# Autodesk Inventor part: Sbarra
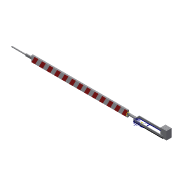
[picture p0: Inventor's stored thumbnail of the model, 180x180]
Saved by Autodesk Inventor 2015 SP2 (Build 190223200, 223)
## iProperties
Created: 2017-10
Part Number: Sbarra
Material: Generico
Document SubType Name: Modeling
Designer: Massimo Pizzirani
Density: 1 g/cm^3
Appearance: Default
Author: Massimo Pizzirani
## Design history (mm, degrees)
sketch "Schizzo1"
  geometry: L1 (250, -125)-(-250, -125); L2 (-250, -125)-(-250, 125); L3 (-250, 125)-(250, 125); L4 (250, 125)-(250, -125); L5 (250, -125)-(-250, 125); L6 (-250, -125)-(250, 125); L7 (1156.676, -150)-(-275, -150); L8 (-275, -150)-(-275, 150); L9 (-275, 150)-(1156.676, 150); L10 (-250, 125)-(1156.676, 125); L11 (-250, -125)-(1156.676, -125); L12 (1156.676, 150)-(1156.676, 125); L13 (1156.676, -125)-(1156.676, -150); 1 further point
  constraints: 26 end point, 3 parallel, 2 midpoint, 2 perpendicular, 2 point on line, 2 vertical, 1 collinear, 1 horizontal
  dimensions: "d0" = 250 distance of L1.end L2.end; "d1" = 500 distance of L1.start L1.end
extrude "Estrusione1" new body sketch "Schizzo1" distance "d3" = 100; taper "d4" = 0 deg
sketch "Schizzo2"
  geometry: L1 (0, 0)-(0, 100) reference; L2 (0, 50)-(1431.676, 50); L3 (1431.676, 0)-(1431.676, 100) reference; C1 r 25 at (500, 50); 1 further point
  constraints: 2 end point, 2 midpoint, 1 centre point, 1 point on line
  dimensions: "d5" = 50 diameter of C1; "d8" = 500 distance from line of L1 C1.centre
extrude "Estrusione2" cut sketch "Schizzo2" stored distance "d6" = 0; taper "d7" = 0 deg
sketch "Schizzo3"
  geometry: L1 (0, 300)-(0, 0) reference; L2 (0, 0)-(100, 0) reference; L3 (100, 300)-(100, 0) reference; L4 (0, 300)-(100, 300) reference; C1 r 50 at (50, 150); 1 further point
  constraints: 1 centre point
extrude "Estrusione3" join sketch "Schizzo3" distance "d9" = 200; taper "d10" = 0 deg
node "Piano di lavoro1"
sketch "Schizzo4"
  geometry: L1 (50, -25)-(-50, -25); L2 (-50, -25)-(-50, 25); L3 (-50, 25)-(50, 25); L4 (50, 25)-(50, -25); L5 (50, -25)-(-50, 25); L6 (-50, -25)-(50, 25); 2 further points
  constraints: 12 end point, 2 midpoint, 2 parallel, 1 horizontal, 1 perpendicular
  dimensions: "d12" = 100 distance of L2.end L3.end; "d13" = 50 distance of L1.end L2.end
loft "Loft1" sketch "Schizzo4" dims "d14" = 0, "d15" = 90 deg, "d16" = 0, "d17" = 90 deg
  node "Spigoli1"
sketch "Schizzo5"
  geometry: L1 (0, 0)-(0, 50) reference; L2 (0, 50)-(-100, 50) reference; L3 (-100, 50)-(-100, 0) reference; L4 (-100, 0)-(0, 0) reference; L5 (0, 50)-(-100, 0); L6 (-200, -10)-(100, -10); L7 (100, -10)-(100, 60); L8 (100, 60)-(-200, 60); L9 (-200, 60)-(-200, -10); L10 (-200, -10)-(100, 60); L11 (100, -10)-(-200, 60); 2 further points
  constraints: 14 end point, 3 midpoint, 2 parallel, 1 horizontal, 1 perpendicular
  dimensions: "d18" = 300 distance of L8.end L7.end; "d19" = 70 distance of L7.end L6.end
extrude "Estrusione4" join sketch "Schizzo5" distance "d20" = 4700.5; taper "d21" = 0 deg
sketch "Schizzo6"
  geometry: L1 (-200, -10)-(100, -10) reference; L2 (100, -10)-(100, 60) reference; L3 (100, 60)-(-200, 60) reference; L4 (-200, 60)-(-200, -10) reference; L5 (100, 60)-(-200, -10); C1 r 25 at (-50, 25); 1 further point
  constraints: 2 end point, 1 centre point, 1 midpoint
  dimensions: "d22" = 50 diameter of C1
extrude "Estrusione5" join sketch "Schizzo6" distance "d23" = 1000; taper "d24" = 0 deg
sketch "Schizzo7"
  geometry: L1 (0, 50)-(-100, 50) reference; L2 (0, 0)-(0, 50) reference; L3 (-100, 50)-(-100, 0) reference; L4 (-100, 0)-(0, 0) reference; 1 further point
extrude "Estrusione6" join sketch "Schizzo7" distance "d25" = 300; taper "d26" = 0 deg
sketch "Schizzo8"
  geometry: L1 (1278.965, 376.869)-(1578.965, 376.869); L2 (1578.965, 376.869)-(1578.965, -23.131); L3 (1578.965, -23.131)-(1278.965, -23.131); L4 (1278.965, -23.131)-(1278.965, 376.869); 1 further point
  constraints: 8 end point, 2 parallel, 1 horizontal, 1 perpendicular
  dimensions: "d27" = 300 distance of L2.end L3.end; "d28" = 400 distance of L1.end L2.end
extrude "Estrusione7" new body sketch "Schizzo8" distance "d29" = 50; taper "d30" = 0 deg
pattern_linear "Serie rettangolare1" dims "d33" = 50.001
sketch "Schizzo9"
  geometry: L1 (-4700.5, 0)-(-4545.135, 300); L2 (0, 300)-(-4700.5, 300) reference; L3 (0, 0)-(-4700.5, 0) reference; L4 (-4516.5, 0)-(-4361.135, 300); L5 (-4700.5, 0)-(-4516.5, 0); L6 (-4545.135, 300)-(-4361.135, 300); 1 further point
  constraints: 8 end point, 3 point on line, 2 collinear, 1 parallel
  dimensions: "d36" = 184 distance of L4.end L1.end
extrude "Estrusione8" join sketch "Schizzo9" distance "d34" = 0.001; taper "d35" = 0 deg
pattern_linear "Serie rettangolare2" dims "d39" = 368
sketch "Schizzo10"
  geometry: L1 (0, 105.941)-(0, 0) reference; L2 (54.865, 0)-(0, 0) reference; L3 (0, 105.941)-(54.865, 0) reference; 1 further point
extrude "Estrusione9" cut sketch "Schizzo10" stored distance "d40" = 0.001; taper "d41" = 0 deg
mirror "Specchio1"
node "Solido1"
node "Linea chiusa proiettata1"
node "Linea chiusa proiettata2"
node "Linea chiusa proiettata3"
node "Solido2"
node "Linea chiusa proiettata4"
